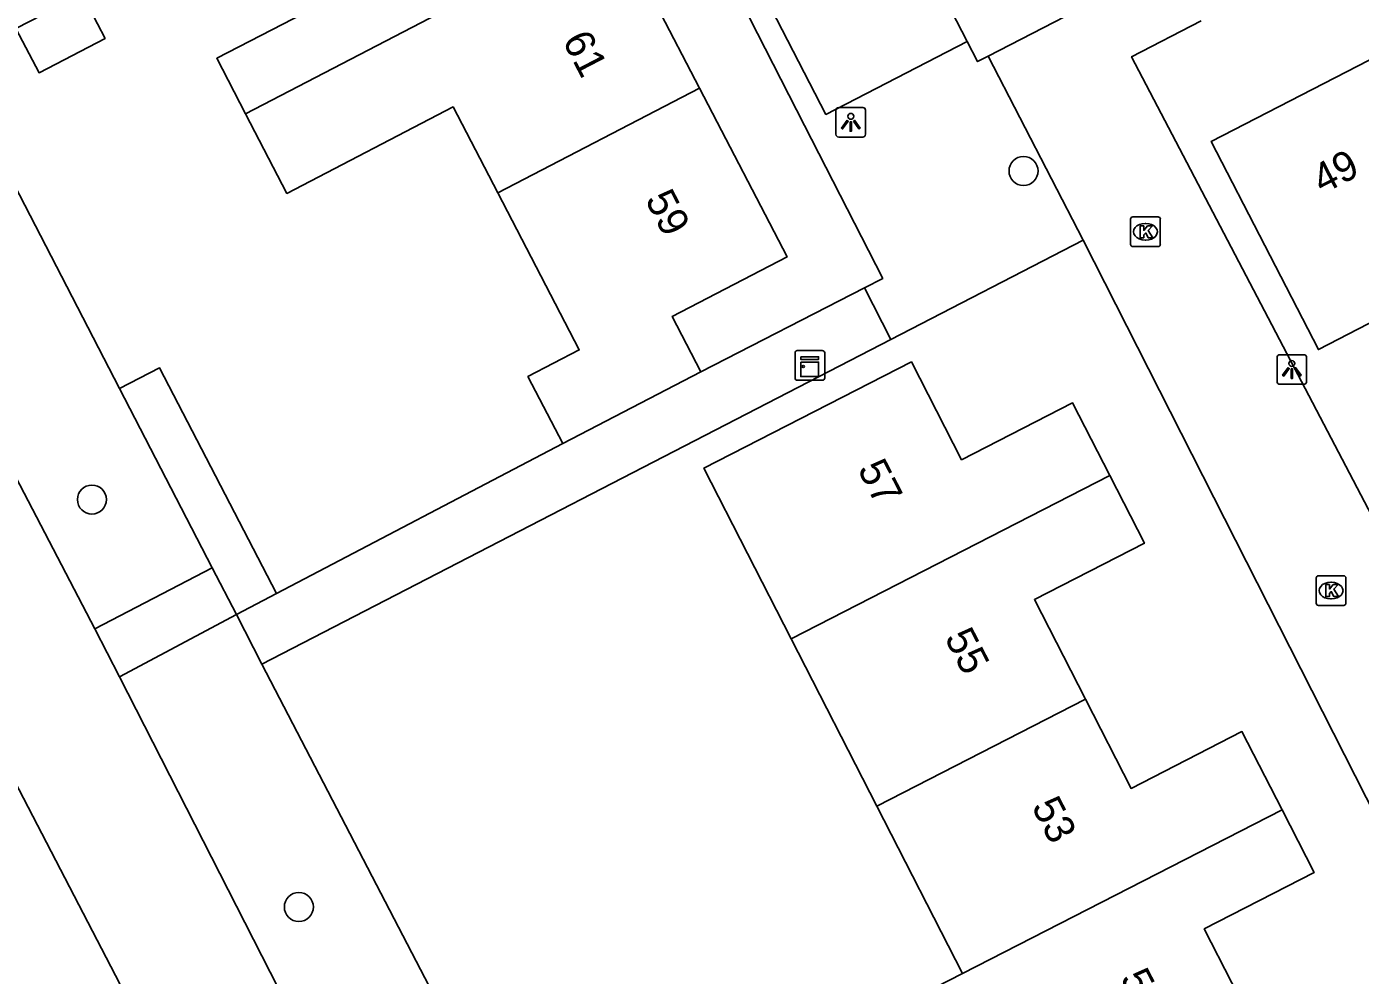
# Model space of a CAD drawing. Extents: x 158461 to 159795, y 387220 to 388672.
# Drawn here: x 159148.3 to 159193.22, y 387818 to 387849.95 of the extents above; entities that cross this region are included whole.
import ezdxf

# ---------------------------------------------------------------- set-up
doc = ezdxf.new("R2010")
doc.units = 0
for name, color, linetype in [('IMGEO_Boom', 7, 'Continuous'), ('IMGEO_Fietspad_gesloten', 7, 'Continuous'), ('IMGEO_Groenvoorziening', 7, 'Continuous'), ('IMGEO_Kast', 7, 'Continuous'), ('IMGEO_Kolk', 7, 'Continuous'), ('IMGEO_Lichtpunt', 7, 'Continuous'), ('IMGEO_Pand', 7, 'Continuous'), ('IMGEO_Pand_nummerreeks', 7, 'Continuous'), ('IMGEO_Rijbaan_lokaal_open', 7, 'Continuous'), ('IMGEO_Voetpad_open', 7, 'Continuous')]:
    doc.layers.add(name, color=color, linetype=linetype)

msp = doc.modelspace()

# ---------------------------------------------------------------- linework, layer by layer
at = {"layer": 'IMGEO_Boom'}
for centre in [(159181.873, 387845.088), (159150.497, 387834.022), (159157.466, 387820.302)]:
    msp.add_circle(centre, 0.489, dxfattribs=at)
at = {"layer": 'IMGEO_Fietspad_gesloten'}
for points in [[(159150.589, 387829.666), (159141.895, 387846.356)], [(159160.411, 387800.428), (159142.468, 387834.978)], [(159151.43, 387828.052), (159150.589, 387829.666)], [(159151.43, 387828.052), (159166.352, 387798.789), (159174.688, 387783.205)]]:
    msp.add_lwpolyline(points, dxfattribs=at)
at = {"layer": 'IMGEO_Groenvoorziening'}
for points in [[(159145.928, 387848.392), (159151.428, 387837.759)], [(159156.222, 387828.474), (159165.575, 387810.485), (159168.211, 387805.415), (159184.183, 387774.695)]]:
    msp.add_lwpolyline(points, dxfattribs=at)
at = {"layer": 'IMGEO_Kast'}
for p, q in [((159174.251, 387839.04), (159175.092, 387839.04)), ((159175.092, 387839.04), (159174.251, 387839.04)), ((159175.176, 387838.965), (159175.176, 387838.124)), ((159175.176, 387838.124), (159175.176, 387838.965)), ((159174.176, 387838.115), (159174.176, 387838.956)), ((159174.176, 387838.956), (159174.176, 387838.115)), ((159175.101, 387838.04), (159174.26, 387838.04)), ((159174.26, 387838.04), (159175.101, 387838.04))]:
    msp.add_line(p, q, dxfattribs=at)
for points in [[(159174.371, 387838.83), (159174.971, 387838.83), (159174.971, 387838.745), (159174.371, 387838.745), (159174.371, 387838.83)], [(159174.371, 387838.655), (159174.971, 387838.655), (159174.971, 387838.166), (159174.371, 387838.166), (159174.371, 387838.655)]]:
    msp.add_lwpolyline(points, dxfattribs=at)
msp.add_circle((159174.455, 387838.504), 0.0377, dxfattribs=at)
for centre, start, end in [((159174.254, 387838.962), 92.4484, 184.2845), ((159174.254, 387838.962), 92.4484, 184.2845), ((159175.098, 387838.962), 2.4484, 94.2845), ((159175.098, 387838.962), 2.4484, 94.2845), ((159174.254, 387838.118), 182.4484, 274.2845), ((159174.254, 387838.118), 182.4484, 274.2845), ((159175.098, 387838.118), 272.4484, 4.2845), ((159175.098, 387838.118), 272.4484, 4.2845)]:
    msp.add_arc(centre, 0.0779, start, end, dxfattribs=at)
at = {"layer": 'IMGEO_Kolk'}
for p, q in [((159185.479, 387842.614), (159185.479, 387843.466)), ((159185.554, 387843.54), (159186.406, 387843.54)), ((159186.48, 387843.466), (159186.48, 387842.614)), ((159185.967, 387843.32), (159185.992, 387843.32)), ((159185.99, 387842.76), (159185.965, 387842.76)), ((159186.406, 387842.54), (159185.554, 387842.54)), ((159191.731, 387830.532), (159191.731, 387831.384)), ((159191.806, 387831.458), (159192.658, 387831.458)), ((159192.732, 387831.384), (159192.732, 387830.532)), ((159192.219, 387831.238), (159192.244, 387831.238)), ((159192.658, 387830.458), (159191.806, 387830.458)), ((159192.242, 387830.678), (159192.217, 387830.678))]:
    msp.add_line(p, q, dxfattribs=at)
for points in [[(159185.479, 387842.614), (159185.479, 387843.466)], [(159185.554, 387843.54), (159186.406, 387843.54)], [(159186.48, 387843.466), (159186.48, 387842.614)], [(159185.8, 387843.24), (159185.923, 387843.24), (159185.923, 387843.089), (159186.053, 387843.24), (159186.217, 387843.24), (159186.071, 387843.089), (159186.224, 387842.84), (159186.072, 387842.84), (159185.987, 387843.004), (159185.923, 387842.937), (159185.923, 387842.84), (159185.8, 387842.84), (159185.8, 387843.24)], [(159186.406, 387842.54), (159185.554, 387842.54)], [(159191.731, 387830.532), (159191.731, 387831.384)], [(159191.806, 387831.458), (159192.658, 387831.458)], [(159192.732, 387831.384), (159192.732, 387830.532)], [(159192.052, 387831.158), (159192.175, 387831.158), (159192.175, 387831.007), (159192.305, 387831.158), (159192.469, 387831.158), (159192.323, 387831.007), (159192.476, 387830.758), (159192.324, 387830.758), (159192.239, 387830.922), (159192.175, 387830.855), (159192.175, 387830.758), (159192.052, 387830.758), (159192.052, 387831.158)], [(159192.658, 387830.458), (159191.806, 387830.458)]]:
    msp.add_lwpolyline(points, dxfattribs=at)
for centre, start, end in [((159185.556, 387843.464), 91.552, 178.448), ((159185.556, 387843.464), 91.552, 178.448), ((159186.404, 387843.464), 1.552, 88.448), ((159186.404, 387843.464), 1.552, 88.448), ((159185.556, 387842.616), 181.552, 268.448), ((159185.556, 387842.616), 181.552, 268.448), ((159186.404, 387842.616), 271.552, 358.448), ((159186.404, 387842.616), 271.552, 358.448), ((159191.808, 387831.382), 91.552, 178.448), ((159191.808, 387831.382), 91.552, 178.448), ((159192.656, 387831.382), 1.552, 88.448), ((159192.656, 387831.382), 1.552, 88.448), ((159191.808, 387830.534), 181.552, 268.448), ((159191.808, 387830.534), 181.552, 268.448), ((159192.656, 387830.534), 271.552, 358.448), ((159192.656, 387830.534), 271.552, 358.448)]:
    msp.add_arc(centre, 0.0765, start, end, dxfattribs=at)
for centre, major_axis, ratio, start_param, end_param in [((159185.966, 387843.04), (-0.387, 0.002), 0.722429, 4.712389, 7.853982), ((159185.991, 387843.04), (-0.39, 0.002), 0.717154, 1.570796, 4.712389), ((159192.218, 387830.958), (-0.387, 0.002), 0.722429, 4.712389, 7.853982), ((159192.243, 387830.958), (-0.39, 0.002), 0.717154, 1.570796, 4.712389)]:
    msp.add_ellipse(centre, major_axis=major_axis, ratio=ratio, start_param=start_param, end_param=end_param, dxfattribs=at)
at = {"layer": 'IMGEO_Lichtpunt'}
for p, q in [((159175.555, 387847.132), (159175.555, 387846.325)), ((159175.555, 387847.132), (159175.555, 387846.325)), ((159176.457, 387847.227), (159175.649, 387847.227)), ((159176.457, 387847.227), (159175.649, 387847.227)), ((159176.551, 387846.325), (159176.551, 387847.132)), ((159176.551, 387846.325), (159176.551, 387847.132)), ((159175.649, 387846.231), (159176.457, 387846.231)), ((159175.649, 387846.231), (159176.457, 387846.231)), ((159190.411, 387838.806), (159190.411, 387837.999)), ((159190.411, 387838.806), (159190.411, 387837.999)), ((159191.313, 387838.901), (159190.505, 387838.901)), ((159191.313, 387838.901), (159190.505, 387838.901)), ((159191.407, 387837.999), (159191.407, 387838.806)), ((159191.407, 387837.999), (159191.407, 387838.806)), ((159190.505, 387837.905), (159191.313, 387837.905)), ((159190.505, 387837.905), (159191.313, 387837.905))]:
    msp.add_line(p, q, dxfattribs=at)
for points in [[(159175.929, 387846.796), (159175.968, 387846.768), (159175.78, 387846.506), (159175.742, 387846.533), (159175.929, 387846.796)], [(159176.031, 387846.748), (159176.078, 387846.748), (159176.078, 387846.426), (159176.031, 387846.426), (159176.031, 387846.748)], [(159176.141, 387846.768), (159176.179, 387846.795), (159176.366, 387846.533), (159176.327, 387846.505), (159176.141, 387846.768)], [(159190.785, 387838.47), (159190.824, 387838.442), (159190.636, 387838.18), (159190.598, 387838.207), (159190.785, 387838.47)], [(159190.887, 387838.422), (159190.934, 387838.422), (159190.934, 387838.1), (159190.887, 387838.1), (159190.887, 387838.422)], [(159190.997, 387838.442), (159191.035, 387838.469), (159191.222, 387838.207), (159191.183, 387838.179), (159190.997, 387838.442)]]:
    msp.add_lwpolyline(points, dxfattribs=at)
for centre in [(159176.054, 387846.93), (159190.91, 387838.604)]:
    msp.add_circle(centre, 0.0994, dxfattribs=at)
for centre, start, end in [((159175.649, 387847.132), 90, 180), ((159175.649, 387847.132), 90, 180), ((159176.457, 387847.132), 0, 90), ((159176.457, 387847.132), 0, 90), ((159175.649, 387846.325), 180, 270), ((159175.649, 387846.325), 180, 270), ((159176.457, 387846.325), 270, 0), ((159176.457, 387846.325), 270, 360), ((159190.505, 387838.806), 90, 180), ((159190.505, 387838.806), 90, 180), ((159191.313, 387838.806), 0, 90), ((159191.313, 387838.806), 0, 90), ((159190.505, 387837.999), 180, 270), ((159190.505, 387837.999), 180, 270), ((159191.313, 387837.999), 270, 0), ((159191.313, 387837.999), 270, 360)]:
    msp.add_arc(centre, 0.0946, start, end, dxfattribs=at)
at = {"layer": 'IMGEO_Pand'}
for points in [[(159155.671, 387847.012), (159154.699, 387848.882), (159159.122, 387851.18), (159157.196, 387854.886)], [(159155.671, 387847.012), (159168.059, 387853.451)], [(159168.059, 387853.451), (159170.955, 387847.877)], [(159147.939, 387849.891), (159150.163, 387851.047), (159150.941, 387849.552), (159148.716, 387848.396), (159147.939, 387849.891)], [(159197.498, 387842.013), (159191.802, 387839.076), (159188.192, 387846.076), (159193.887, 387849.013)], [(159170.955, 387847.877), (159164.165, 387844.348)], [(159170.955, 387847.877), (159173.907, 387842.196), (159170.035, 387840.184), (159171, 387838.328)], [(159164.165, 387844.348), (159162.66, 387847.245), (159157.061, 387844.335), (159155.671, 387847.012)], [(159166.354, 387835.914), (159165.183, 387838.167), (159166.911, 387839.065), (159164.165, 387844.348)], [(159174.049, 387829.333), (159171.106, 387835.081), (159178.098, 387838.661), (159179.786, 387835.364), (159183.526, 387837.278), (159184.778, 387834.833)], [(159171, 387838.328), (159166.354, 387835.914)], [(159174.049, 387829.333), (159184.778, 387834.833)], [(159184.778, 387834.833), (159185.947, 387832.55), (159182.241, 387830.652), (159183.959, 387827.296)], [(159176.935, 387823.696), (159174.049, 387829.333)], [(159176.935, 387823.696), (159183.959, 387827.296)], [(159183.959, 387827.296), (159185.494, 387824.298), (159189.229, 387826.21), (159190.579, 387823.573)], [(159179.821, 387818.059), (159176.935, 387823.696)], [(159190.579, 387823.573), (159191.661, 387821.459), (159187.959, 387819.563), (159189.818, 387815.932), (159182.76, 387812.318), (159179.518, 387810.658), (159176.578, 387816.399), (159179.821, 387818.059)], [(159190.579, 387823.573), (159179.821, 387818.059)]]:
    msp.add_lwpolyline(points, dxfattribs=at)
at = {"layer": 'IMGEO_Rijbaan_lokaal_open'}
for points in [[(159176.512, 387841.15), (159177.134, 387841.469), (159174.5, 387846.623), (159155.484, 387883.835)], [(159179.976, 387849.448), (159175.217, 387846.993), (159168.051, 387860.883), (159172.809, 387863.339)], [(159172.809, 387863.339), (159179.976, 387849.448)], [(159180.682, 387848.954), (159185.473, 387851.432)], [(159187.86, 387850.144), (159185.514, 387848.933), (159196.467, 387828.005), (159197.412, 387828.453), (159201.093, 387830.322)], [(159179.976, 387849.448), (159180.326, 387848.77), (159180.682, 387848.954)], [(159180.682, 387848.954), (159183.884, 387842.763)], [(159183.884, 387842.763), (159177.399, 387839.413)], [(159196.339, 387818.215), (159183.884, 387842.763)], [(159177.399, 387839.413), (159176.512, 387841.15)]]:
    msp.add_lwpolyline(points, dxfattribs=at)
at = {"layer": 'IMGEO_Voetpad_open'}
for points in [[(159176.512, 387841.15), (159171, 387838.328)], [(159177.399, 387839.413), (159156.222, 387828.474)], [(159151.428, 387837.759), (159152.778, 387838.458), (159156.71, 387830.857)], [(159151.428, 387837.759), (159154.548, 387831.728)], [(159156.71, 387830.857), (159166.354, 387835.914)], [(159150.589, 387829.666), (159154.548, 387831.728)], [(159154.548, 387831.728), (159155.364, 387830.151)], [(159155.364, 387830.151), (159156.71, 387830.857)], [(159155.364, 387830.151), (159151.43, 387828.052)], [(159156.222, 387828.474), (159155.364, 387830.151)]]:
    msp.add_lwpolyline(points, dxfattribs=at)

# ---------------------------------------------------------------- texts
at = {"layer": 'IMGEO_Pand_nummerreeks'}
for s, rotation, p in [('61', 297.4559, (159166.326, 387849.482)), ('49', 27.2809, (159191.933, 387844.289)), ('59', 297.4559, (159169.111, 387844.128)), ('57', 297.2775, (159176.268, 387835.052)), ('55', 297.2775, (159179.198, 387829.37)), ('53', 297.2775, (159182.128, 387823.687)), ('51', 297.2783, (159185.11, 387817.903))]:
    msp.add_text(s, height=1, rotation=rotation, dxfattribs=at).set_placement(p)

doc.saveas('drawing.dxf')
